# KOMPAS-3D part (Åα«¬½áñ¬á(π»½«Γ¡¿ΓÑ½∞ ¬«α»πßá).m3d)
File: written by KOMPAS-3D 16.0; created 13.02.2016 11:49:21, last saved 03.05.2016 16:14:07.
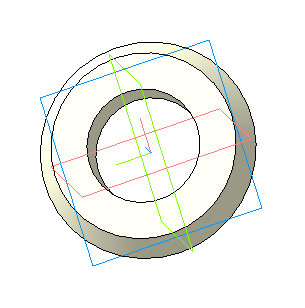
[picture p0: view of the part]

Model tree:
1. Эскиз:1
2. Операция выдавливания:1
     Расстояние 1 = 12
3. Эскиз:2
4. Вырезать элемент выдавливания:1
     Расстояние 1 = 14; Угол 1 = 2
5. Эскиз:3
6. Вырезать элемент выдавливания:2
     Расстояние 1 = 4.5
7. Уклон:1
     Угол уклона = 30
8. Эскиз:4
9. Вырезать элемент выдавливания:3
     Расстояние 1 = 2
